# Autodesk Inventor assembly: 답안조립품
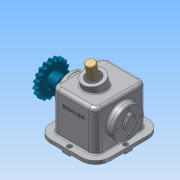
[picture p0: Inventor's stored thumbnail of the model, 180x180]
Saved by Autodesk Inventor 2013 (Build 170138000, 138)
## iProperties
Created: 2014-11
Part Number: 답안조립품
Document SubType Name: Assembly
Designer: Administrator
Author: Administrator
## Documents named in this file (13)
- C:\Users\Administrator\Desktop\441123V1011\답안조립품.iam
- C:\Users\Administrator\Desktop\441123V1011\본체.ipt
- C:\Users\Administrator\Desktop\441123V1011\5-체인 스프로킷.ipt
- C:\Users\Administrator\Desktop\441123V1011\M4x0.5.ipt
- C:\Users\Administrator\Desktop\441123V1011\뒤커버.ipt
- C:\Users\Administrator\Desktop\441123V1011\멈춤나사 M5x0.5.ipt
- C:\Users\Administrator\Desktop\441123V1011\베어링 6205.ipt
- C:\Users\Administrator\Desktop\441123V1011\부시.ipt
- C:\Users\Administrator\Desktop\441123V1011\슬라이드.ipt
- C:\Users\Administrator\Desktop\441123V1011\앞커버.ipt
- C:\Users\Administrator\Desktop\441123V1011\오일실.ipt
- C:\Users\Administrator\Desktop\441123V1011\키 8x8.ipt
- C:\Users\Administrator\Desktop\441123V1011\편심축.ipt
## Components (9 placed, 2 different names)
1. 5-체인 스프로킷:1 — Mate:2, Mate:8, Mate:9
2. M4x0.5:2 — Mate:15, Mate:16
3. M4x0.5:3
4. M4x0.5:4
5. M4x0.5:5
6. M4x0.5:1 — Mate:22, Mate:23
7. M4x0.5:6
8. M4x0.5:7
9. M4x0.5:8
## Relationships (7: Mate 7)
- Mate:2: 5-체인 스프로킷:1
- Mate:8: 5-체인 스프로킷:1
- Mate:9: 5-체인 스프로킷:1
- Mate:15: M4x0.5:2
- Mate:16: M4x0.5:2
- Mate:22: M4x0.5:1
- Mate:23: M4x0.5:1
